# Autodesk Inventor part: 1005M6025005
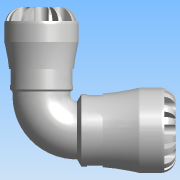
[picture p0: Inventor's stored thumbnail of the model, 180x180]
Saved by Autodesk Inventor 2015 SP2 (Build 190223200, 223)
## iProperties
Created: 2016-12
Part Number: 1005M6025005
Material: PVC-Piping
Description: PLASSON 90° ELBOW METRIC TO IMPERIAL 25X1/2" SERIES 1
Document SubType Name: Modeling
Designer: KIM
Mass: 664.223 g
Surface Area: 733.008 cm^2
Volume: 474.445 cm^3
Density: 1.4 g/cm^3
Appearance: Smooth - White
Author: KIM
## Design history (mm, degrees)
derived "1005M.ipt"
feature "Solid1::1005M.ipt"
tag "TaggingFeature1"
body "Solid1"
other parameters: "d9" = 7.875, "d11" = 47, "d12" = 31.25, "d230" = 41, "d231" = 21.59, "d232" = 9.705, "d1" = 20.16, "d2" = 25, "d3" = 31.25, "d4" = 47, "d8" = 39.95, "d13" = 6.3, "d14" = 6.3, "d15" = 0, "d17" = 360 deg, "d19" = 8 deg, "d20" = 0.5, "d21" = 0.5, "d22" = 8 deg, "d24" = 0, "d26" = 360 deg, "d33" = 4.7, "d43" = 36.66, "d51" = 0.47, "d54" = 8.75, "d55" = 5.5, "d57" = 12.348, "d58" = 0, "d74" = 0, "d77" = 2.08333, "d78" = 48, "d82" = 0.5, "d115" = 360 deg, "d207" = 90 deg, "d209" = 19.32, "d210" = 12.7, "d211" = 21.59, "d212" = 41, "d213" = 34.85, "d215" = 31.98, "d216" = 1.05833, "d217" = 46, "d226" = 46, "d228" = 7.4375, "d229" = 7.764, "d233" = 7.764, "d234" = 0, "d236" = 360 deg, "d238" = 8 deg, "d239" = 8 deg, "d240" = 0.5, "d241" = 0.5, "d243" = 0, "d245" = 360 deg, "d248" = 2.88, "d249" = 2.76, "d250" = 7.4375, "d252" = 8.75, "d253" = 5.75, "d254" = 12.348, "d255" = 0, "d257" = 360 deg, "d259" = 0.5, "d261" = 0, "d262" = 0.94, "d268" = 0, "d269" = 74, "d270" = 2.76, "d271" = 21.9725, "d272" = 68, "d285" = 0, "d286" = 0, "d288" = 3.985, "d290" = 30 deg, "d291" = 0.41, "d_" = 25, "E_" = 47, "l_" = 48, "A_1" = 68, "A_" = 74, "d_1" = 12.7, "E_1" = 41, "l_1" = 46
